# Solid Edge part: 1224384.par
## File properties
Title: M20 FORM C WASHER
Author: TraceParts S.A.
Template: Iso Metric Part.par
Last saved by: Nimesh.N
Revision: 3
Application: TraceParts
Company: TraceParts S.A.
Density: 7833.000 kg/m^3
Accuracy: 0.990
REFERENCE: 1224384
rs_stock_number: 1224384
url: https://uk.rs-online.com/web/p/products/1224384//?cm_mmc=aff-_-uk-_-traceparts-_-1224384'
SUPPLIER: RS Pro
DESIGN: M20 FORM C WASHER
TraceParts.PartNumber: 90-27102023-075854
TraceParts.InstanceId: 90-27102023-07585478P2ST6ENTHNY6M228NL8S6AD
TraceParts.PartTitle: M20 FORM C WASHER
TRACEPARTS: TRACEPARTS
TraceParts.PartLanguage: en
TraceParts.PartVersion: 1.0.0
Username: Nimesh.N
Material: Steel
Face Style: Black (dull)
Fill Style: ANSI32(Steel)
Virtual Style: ANSI32(Steel)
Grouping: Metals\Steel
LibraryName: Materials
Coef. of Thermal Exp: 1.3e-05
Thermal Conductivity: 32.0
Specific Heat: 481.0
Modulus of Elasticity: 199947953000.0
Poisson's Ratio: 0.29
Yield Stress: 262000766.0
Ultimate Stress: 358527364.0
Elongation: 0.0
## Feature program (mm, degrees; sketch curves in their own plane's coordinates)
body "unnamed Body 1"
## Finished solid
Body 1: solid body, 4 faces, 4 edges, 4 vertices.
  Faces by surface: cylinder 2, plane 2
  Edges by curve: circle 4
Bounding box of the edges (mm): 39.000 x 39.000 x 3.000, from (-19.5, -19.5, 0) to (19.5, 19.5, 3).
Cylindrical faces by radius (mm): R10.5 x1, R19.5 x1
Planar faces by outward normal: +z 1, -z 1
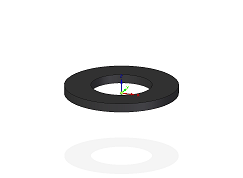
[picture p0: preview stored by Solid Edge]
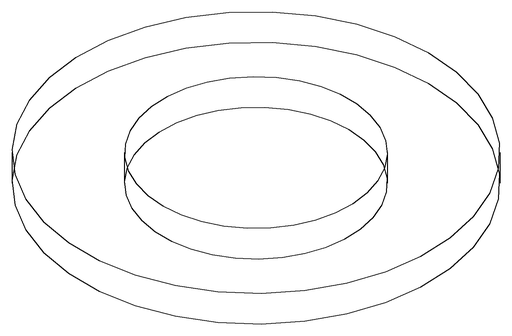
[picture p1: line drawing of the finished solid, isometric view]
